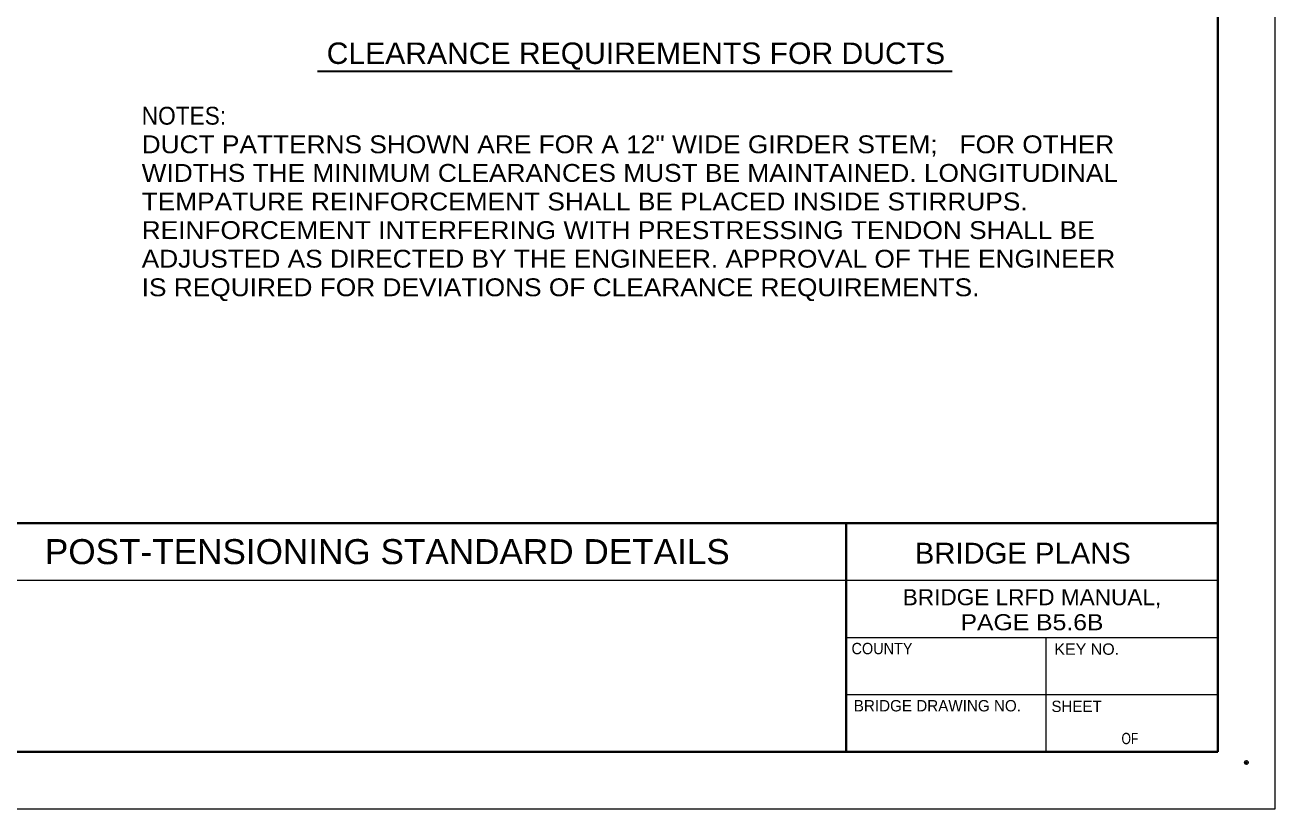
# Model space of a CAD drawing. Extents: x 0 to 22.7, y 0 to 15.6.
# Drawn here: x 15.38 to 22.67, y 0 to 4.57 of the extents above; entities that cross this region are included whole.
import ezdxf
from ezdxf.enums import TextEntityAlignment as Align

# ---------------------------------------------------------------- set-up
doc = ezdxf.new("R2010")
doc.units = 0
doc.header["$LTSCALE"] = 0.042
doc.header["$PDMODE"] = 32
doc.header["$PDSIZE"] = 0.021
doc.layers.add('1', color=7, linetype='Continuous', lineweight=13)
doc.layers.add('4', color=7, linetype='Continuous', lineweight=13)
doc.layers.add('49', color=7, linetype='Continuous')

msp = doc.modelspace()

# ---------------------------------------------------------------- linework, layer by layer
at = {"layer": '1', "lineweight": 35}
msp.add_line((17.08479, 4.30099), (20.7838, 4.30099), dxfattribs=at)
at = {"layer": '1', "lineweight": 40}
for p, q in [((12.83333, 1.66667), (22.33333, 1.66667)), ((20.16667, 0.33333), (20.16667, 1.66667))]:
    msp.add_line(p, q, dxfattribs=at)
at = {"layer": '1'}
for p, q in [((14.83333, 1.33333), (22.33333, 1.33333)), ((20.16667, 1), (22.33333, 1)), ((21.33333, 0.33333), (21.33333, 1)), ((20.16667, 0.66667), (22.33333, 0.66667))]:
    msp.add_line(p, q, dxfattribs=at)
msp.add_lwpolyline([(0, 0), (22.66667, 0), (22.66667, 14.66667), (0, 14.66667)], close=True, dxfattribs=at)
at = {"layer": '1', "lineweight": 40}
msp.add_lwpolyline([(22.33333, 0.33333), (22.33333, 14.33333), (1, 14.33333), (1, 0.33333)], close=True, dxfattribs=at)
at = {"layer": '49'}
msp.add_point((22.5, 0.27083), dxfattribs=at)

# ---------------------------------------------------------------- texts
at = {"layer": '1', "width": 1.1}
for s, p in [('ADJUSTED AS DIRECTED BY THE ENGINEER. APPROVAL OF THE ENGINEER', (16.05995, 3.15531)), ('IS REQUIRED FOR DEVIATIONS OF CLEARANCE REQUIREMENTS.', (16.05995, 2.98865))]:
    msp.add_text(s, height=0.1041, dxfattribs=at).set_placement(p)
at = {"layer": '4'}
for s, height, width, p in [('CLEARANCE REQUIREMENTS FOR DUCTS', 0.1249, 1.05, (18.94104, 4.34255)), ('POST-TENSIONING STANDARD DETAILS', 0.1458, 1.05, (17.49198, 1.42708)), ('BRIDGE PLANS', 0.1213, 1.05, (21.19651, 1.43042)), ('BRIDGE LRFD MANUAL,', 0.09375, 1.05, (21.25, 1.1875)), ('PAGE B5.6B', 0.09375, 1.15, (21.25003, 1.04167)), ('COUNTY', 0.06625, 0.95, (20.37581, 0.90208)), ('KEY NO.', 0.06625, 1.05, (21.56914, 0.89875)), ('OF', 0.06583, 0.8, (21.82083, 0.37792))]:
    msp.add_text(s, height=height, dxfattribs=dict(at, width=width)).set_placement(p, align=Align.CENTER)
for s, width, p in [('NOTES:', 0.95, (16.05995, 3.98865)), ('DUCT PATTERNS SHOWN ARE FOR A 12" WIDE GIRDER STEM;   FOR OTHER', 1.1, (16.05995, 3.82198)), ('WIDTHS THE MINIMUM CLEARANCES MUST BE MAINTAINED. LONGITUDINAL', 1.1, (16.05995, 3.65531)), ('TEMPATURE REINFORCEMENT SHALL BE PLACED INSIDE STIRRUPS.', 1.1, (16.05995, 3.48865)), ('REINFORCEMENT INTERFERING WITH PRESTRESSING TENDON SHALL BE', 1.1, (16.05995, 3.32198))]:
    msp.add_text(s, height=0.1041, dxfattribs=dict(at, width=width)).set_placement(p)
for s, height, p in [('BRIDGE DRAWING NO.', 0.06625, (20.69839, 0.56875)), ('SHEET', 0.06583, (21.51, 0.56542))]:
    msp.add_text(s, height=height, dxfattribs=at).set_placement(p, align=Align.CENTER)

doc.saveas('drawing.dxf')
